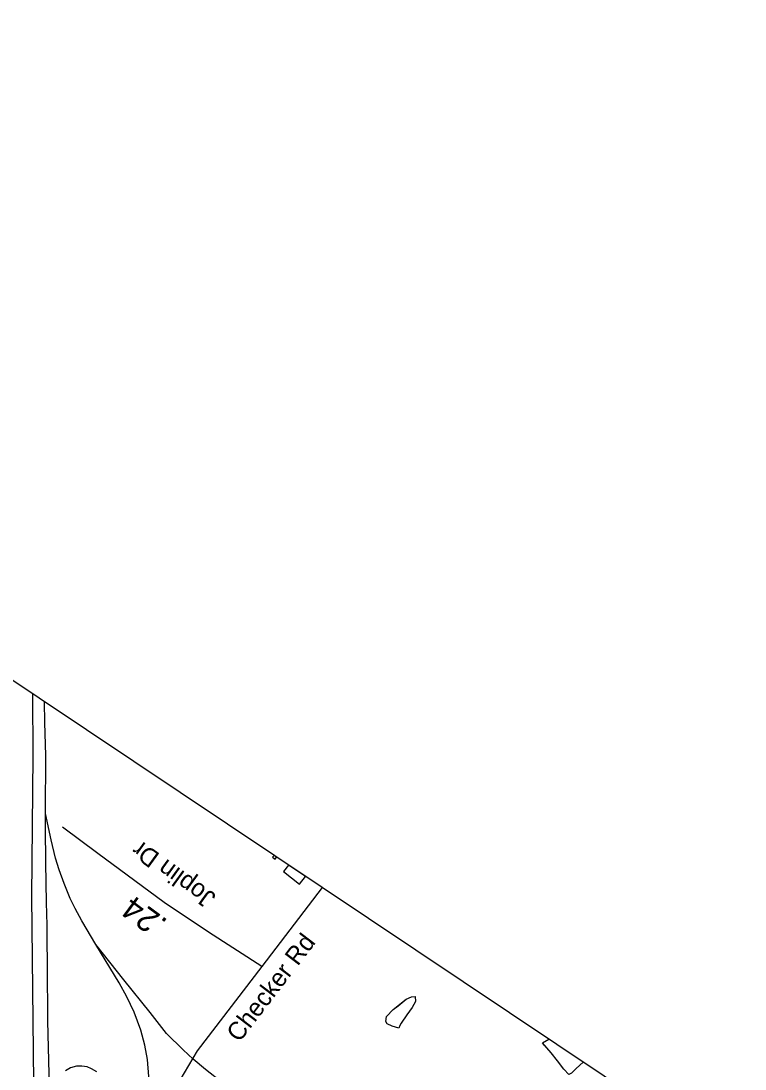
# Model space of a CAD drawing. Extents: x 1715610 to 1720914, y 798298 to 802505.
# Drawn here: x 1716167.3 to 1716250.5, y 799705.3 to 799825.8 of the extents above; entities that cross this region are included whole.
import ezdxf

# ---------------------------------------------------------------- set-up
doc = ezdxf.new("R2010")
doc.units = 0
doc.layers.add('Default', color=7, linetype='Continuous')
doc.layers.add('Prop DSN Text', color=7, linetype='Continuous')

msp = doc.modelspace()

# ---------------------------------------------------------------- linework, layer by layer
at = {"layer": 'Default'}
for p, q in [((1716196.68, 799729.69), (1716196.39, 799729.89)), ((1716199.99, 799727.48), (1716198.06, 799728.77))]:
    msp.add_line(p, q, dxfattribs=at)
for points in [[(1716169.74, 799648.17), (1716169.53, 799660.65), (1716168.86, 799675.82), (1716168.85, 799692.22), (1716168.7, 799700.54), (1716168.77, 799703.78), (1716168.56, 799725.16), (1716168.72, 799741.3), (1716168.68, 799748.44)], [(1716170.14, 799734.71), (1716170.18, 799741.36), (1716170.06, 799745.16), (1716170.01, 799747.54)], [(1716170.65, 799699.78), (1716170.51, 799703.13), (1716170.56, 799704.77), (1716170.38, 799710.84), (1716170.38, 799712.39), (1716170.36, 799715.69), (1716170.32, 799721.85), (1716170.25, 799724.49), (1716170.17, 799729.05), (1716170.11, 799733.07), (1716170.14, 799734.71)], [(1716175.91, 799719.65), (1716174.32, 799722.38), (1716173.52, 799723.78), (1716172.97, 799724.94), (1716172.27, 799726.67), (1716171.69, 799728.23), (1716171.28, 799729.56), (1716170.77, 799731.67), (1716170.14, 799734.71)], [(1716194.98, 799717.11), (1716188.84, 799721.07), (1716183.76, 799724.47), (1716176.13, 799730.1), (1716172.07, 799733.12)], [(1716196.39, 799729.89), (1716196.23, 799729.69), (1716196.51, 799729.47), (1716196.68, 799729.69)], [(1716198.06, 799728.77), (1716197.48, 799728.02), (1716199.3, 799726.6), (1716199.99, 799727.48)], [(1716201.92, 799726.19), (1716194.98, 799717.11)], [(1716170.91, 799685.72), (1716173.52, 799687.26), (1716174.81, 799688.35), (1716176.37, 799689.71), (1716177.98, 799691.58), (1716178.85, 799692.94), (1716179.72, 799694.42), (1716181.7, 799699.58), (1716182.13, 799703), (1716181.84, 799706.43), (1716181.54, 799708.09), (1716181.08, 799709.81), (1716180.33, 799711.87), (1716179.49, 799713.63), (1716178.61, 799715.23), (1716175.91, 799719.65)], [(1716187.08, 799706.46), (1716185.95, 799707.55), (1716184.05, 799709.42), (1716182.16, 799711.82), (1716179.13, 799715.57), (1716175.91, 799719.65)], [(1716194.98, 799717.11), (1716187.57, 799707.41), (1716185.55, 799704.06), (1716184.22, 799701.07), (1716183.47, 799697.69), (1716183.21, 799694.41), (1716183.67, 799690.76), (1716184.32, 799686.45), (1716185.57, 799679.93), (1716187.29, 799674.86)], [(1716210.74, 799710.03), (1716209.95, 799710.25), (1716209.4, 799710.52), (1716209.22, 799710.8), (1716209.3, 799711.38), (1716210.09, 799712.16), (1716210.66, 799712.61), (1716211.59, 799713.35), (1716212.2, 799713.62), (1716212.59, 799713.66), (1716212.64, 799713.11), (1716212.27, 799712.41), (1716211.64, 799711.57), (1716210.98, 799710.6), (1716210.84, 799710.32), (1716210.74, 799710.03)], [(1716210.74, 799710.03), (1716209.95, 799710.25), (1716209.4, 799710.52), (1716209.22, 799710.8), (1716209.3, 799711.38), (1716210.09, 799712.16), (1716211.59, 799713.35), (1716212.2, 799713.62), (1716212.59, 799713.66), (1716212.64, 799713.11), (1716212.27, 799712.41), (1716211.64, 799711.57), (1716210.98, 799710.6), (1716210.84, 799710.32), (1716210.74, 799710.03)], [(1716227.24, 799708.34), (1716227.97, 799708.75)], [(1716227.24, 799708.34), (1716227.98, 799708.75)], [(1716231.91, 799706.12), (1716231.09, 799705.4), (1716230.56, 799704.86), (1716230.28, 799704.69), (1716229.7, 799705.3), (1716228.95, 799706.29), (1716228.25, 799707.18), (1716227.5, 799708.01), (1716227.24, 799708.34)], [(1716231.91, 799706.12), (1716231.09, 799705.4), (1716230.56, 799704.86), (1716230.28, 799704.69), (1716229.7, 799705.3), (1716228.95, 799706.29), (1716228.25, 799707.18), (1716227.24, 799708.34)], [(1716209.45, 799696.49), (1716203.12, 799697.9), (1716197.45, 799699.98), (1716194.6, 799701.21), (1716192.01, 799702.74), (1716190.47, 799703.73), (1716188.53, 799705.26), (1716187.08, 799706.46)], [(1716176.02, 799705), (1716175.42, 799705.37), (1716174.91, 799705.57), (1716174.3, 799705.66), (1716173.69, 799705.64), (1716172.99, 799705.46), (1716172.44, 799705.14)]]:
    msp.add_lwpolyline(points, dxfattribs=at)
at = {"layer": 'Prop DSN Text'}
msp.add_lwpolyline([(1715972.32, 799278.02), (1716250.51, 799693.66), (1715888.23, 799936.14), (1715610.03, 799520.5)], close=True, dxfattribs=at)

# ---------------------------------------------------------------- texts
at = {"layer": 'Default'}
for s, height, rotation, p in [('Joplin Dr', 2.066, 144.0963, (1716189.85, 799725.32)), ('.24', 2.719, 143.5666, (1716184.29, 799722.39)), ('Checker Rd', 2.066, 52.6141, (1716192.4, 799708.3))]:
    msp.add_text(s, height=height, rotation=rotation, dxfattribs=at).set_placement(p)

doc.saveas('drawing.dxf')
